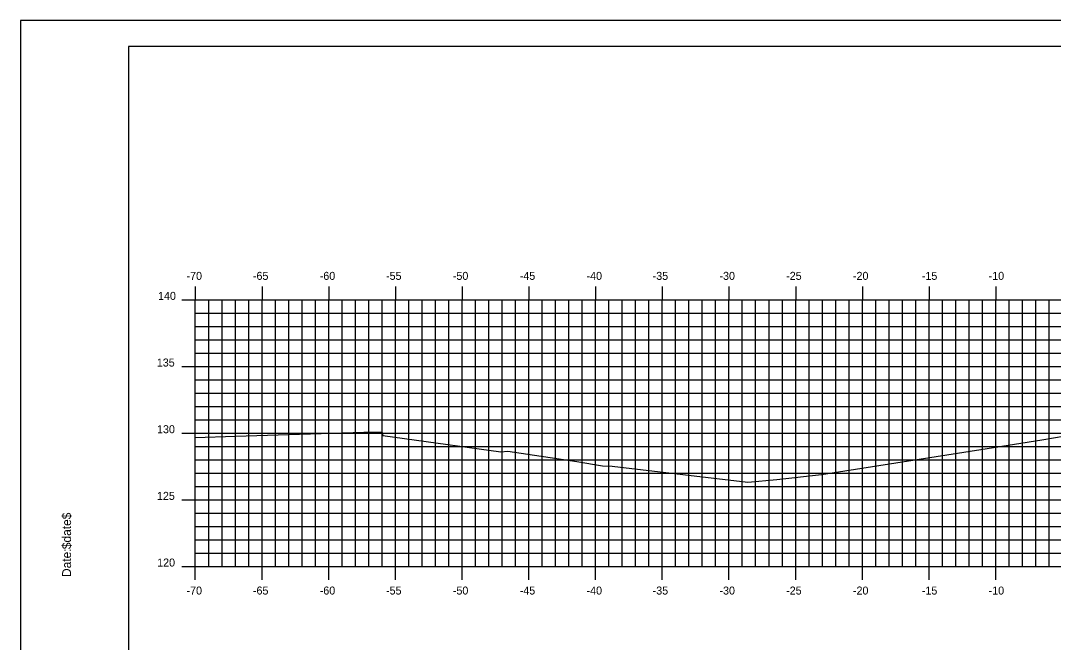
# Model space of a CAD drawing. Extents: x 850851 to 851023, y 365624 to 365734.
# Drawn here: x 850851.4 to 850928.8, y 365687.3 to 365734 of the extents above; entities that cross this region are included whole.
import ezdxf

# ---------------------------------------------------------------- set-up
doc = ezdxf.new("R2010")
doc.units = 0
for name, color, linetype in [('BORDER', 7, 'Continuous'), ('H_V ANNOTATION', 7, 'Continuous'), ('MAJOR', 7, 'Continuous'), ('MINOR', 7, 'Continuous'), ('PLOT BOUNDARY', 7, 'Continuous'), ('S_Roadway_Centerline', 7, 'Continuous')]:
    doc.layers.add(name, color=color, linetype=linetype)

msp = doc.modelspace()

# ---------------------------------------------------------------- linework, layer by layer
at = {"layer": 'BORDER'}
msp.add_lwpolyline([(850859.496, 365627.027), (851019.496, 365627.027), (851019.496, 365732.027), (850859.496, 365732.027)], close=True, dxfattribs=at)
at = {"layer": 'MAJOR'}
for p, q in [((850864.496, 365714.029), (850864.496, 365713.027)), ((850869.496, 365714.029), (850869.496, 365713.027)), ((850874.496, 365714.029), (850874.496, 365713.027)), ((850879.496, 365714.029), (850879.496, 365713.027)), ((850884.496, 365714.029), (850884.496, 365713.027)), ((850889.496, 365714.029), (850889.496, 365713.027)), ((850894.496, 365714.029), (850894.496, 365713.027)), ((850899.496, 365714.029), (850899.496, 365713.027)), ((850904.496, 365714.029), (850904.496, 365713.027)), ((850909.496, 365714.029), (850909.496, 365713.027)), ((850914.496, 365714.029), (850914.496, 365713.027)), ((850919.496, 365714.029), (850919.496, 365713.027)), ((850924.496, 365714.029), (850924.496, 365713.027)), ((850863.494, 365713.027), (850864.496, 365713.027)), ((850864.496, 365713.027), (851004.496, 365713.027)), ((850864.496, 365693.027), (850864.496, 365713.027)), ((850864.496, 365693.027), (850864.496, 365713.027)), ((850864.496, 365713.027), (851004.496, 365713.027)), ((850869.496, 365693.027), (850869.496, 365713.027)), ((850874.496, 365693.027), (850874.496, 365713.027)), ((850879.496, 365693.027), (850879.496, 365713.027)), ((850884.496, 365693.027), (850884.496, 365713.027)), ((850889.496, 365693.027), (850889.496, 365713.027)), ((850894.496, 365693.027), (850894.496, 365713.027)), ((850899.496, 365693.027), (850899.496, 365713.027)), ((850904.496, 365693.027), (850904.496, 365713.027)), ((850909.496, 365693.027), (850909.496, 365713.027)), ((850914.496, 365693.027), (850914.496, 365713.027)), ((850919.496, 365693.027), (850919.496, 365713.027)), ((850924.496, 365693.027), (850924.496, 365713.027)), ((850863.494, 365708.027), (850864.496, 365708.027)), ((850864.496, 365708.027), (851004.496, 365708.027)), ((850863.494, 365703.027), (850864.496, 365703.027)), ((850864.496, 365703.027), (851004.496, 365703.027)), ((850863.494, 365698.027), (850864.496, 365698.027)), ((850864.496, 365698.027), (851004.496, 365698.027)), ((850863.494, 365693.027), (850864.496, 365693.027)), ((850864.496, 365693.027), (851004.496, 365693.027)), ((850864.496, 365693.027), (851004.496, 365693.027)), ((850864.496, 365692.025), (850864.496, 365693.027)), ((850869.496, 365692.025), (850869.496, 365693.027)), ((850874.496, 365692.025), (850874.496, 365693.027)), ((850879.496, 365692.025), (850879.496, 365693.027)), ((850884.496, 365692.025), (850884.496, 365693.027)), ((850889.496, 365692.025), (850889.496, 365693.027)), ((850894.496, 365692.025), (850894.496, 365693.027)), ((850899.496, 365692.025), (850899.496, 365693.027)), ((850904.496, 365692.025), (850904.496, 365693.027)), ((850909.496, 365692.025), (850909.496, 365693.027)), ((850914.496, 365692.025), (850914.496, 365693.027)), ((850919.496, 365692.025), (850919.496, 365693.027)), ((850924.496, 365692.025), (850924.496, 365693.027))]:
    msp.add_line(p, q, dxfattribs=at)
at = {"layer": 'MINOR'}
for p, q in [((850865.496, 365693.027), (850865.496, 365713.027)), ((850866.496, 365693.027), (850866.496, 365713.027)), ((850867.496, 365693.027), (850867.496, 365713.027)), ((850868.496, 365693.027), (850868.496, 365713.027)), ((850870.496, 365693.027), (850870.496, 365713.027)), ((850871.496, 365693.027), (850871.496, 365713.027)), ((850872.496, 365693.027), (850872.496, 365713.027)), ((850873.496, 365693.027), (850873.496, 365713.027)), ((850875.496, 365693.027), (850875.496, 365713.027)), ((850876.496, 365693.027), (850876.496, 365713.027)), ((850877.496, 365693.027), (850877.496, 365713.027)), ((850878.496, 365693.027), (850878.496, 365713.027)), ((850880.496, 365693.027), (850880.496, 365713.027)), ((850881.496, 365693.027), (850881.496, 365713.027)), ((850882.496, 365693.027), (850882.496, 365713.027)), ((850883.496, 365693.027), (850883.496, 365713.027)), ((850885.496, 365693.027), (850885.496, 365713.027)), ((850886.496, 365693.027), (850886.496, 365713.027)), ((850887.496, 365693.027), (850887.496, 365713.027)), ((850888.496, 365693.027), (850888.496, 365713.027)), ((850890.496, 365693.027), (850890.496, 365713.027)), ((850891.496, 365693.027), (850891.496, 365713.027)), ((850892.496, 365693.027), (850892.496, 365713.027)), ((850893.496, 365693.027), (850893.496, 365713.027)), ((850895.496, 365693.027), (850895.496, 365713.027)), ((850896.496, 365693.027), (850896.496, 365713.027)), ((850897.496, 365693.027), (850897.496, 365713.027)), ((850898.496, 365693.027), (850898.496, 365713.027)), ((850900.496, 365693.027), (850900.496, 365713.027)), ((850901.496, 365693.027), (850901.496, 365713.027)), ((850902.496, 365693.027), (850902.496, 365713.027)), ((850903.496, 365693.027), (850903.496, 365713.027)), ((850905.496, 365693.027), (850905.496, 365713.027)), ((850906.496, 365693.027), (850906.496, 365713.027)), ((850907.496, 365693.027), (850907.496, 365713.027)), ((850908.496, 365693.027), (850908.496, 365713.027)), ((850910.496, 365693.027), (850910.496, 365713.027)), ((850911.496, 365693.027), (850911.496, 365713.027)), ((850912.496, 365693.027), (850912.496, 365713.027)), ((850913.496, 365693.027), (850913.496, 365713.027)), ((850915.496, 365693.027), (850915.496, 365713.027)), ((850916.496, 365693.027), (850916.496, 365713.027)), ((850917.496, 365693.027), (850917.496, 365713.027)), ((850918.496, 365693.027), (850918.496, 365713.027)), ((850920.496, 365693.027), (850920.496, 365713.027)), ((850921.496, 365693.027), (850921.496, 365713.027)), ((850922.496, 365693.027), (850922.496, 365713.027)), ((850923.496, 365693.027), (850923.496, 365713.027)), ((850925.496, 365693.027), (850925.496, 365713.027)), ((850926.496, 365693.027), (850926.496, 365713.027)), ((850927.496, 365693.027), (850927.496, 365713.027)), ((850928.496, 365693.027), (850928.496, 365713.027)), ((850864.496, 365712.027), (851004.496, 365712.027)), ((850864.496, 365712.027), (850865.498, 365712.027)), ((850864.496, 365711.027), (851004.496, 365711.027)), ((850864.496, 365711.027), (850865.498, 365711.027)), ((850864.496, 365710.027), (851004.496, 365710.027)), ((850864.496, 365710.027), (850865.498, 365710.027)), ((850864.496, 365709.027), (851004.496, 365709.027)), ((850864.496, 365709.027), (850865.498, 365709.027)), ((850864.496, 365707.027), (851004.496, 365707.027)), ((850864.496, 365707.027), (850865.498, 365707.027)), ((850864.496, 365706.027), (851004.496, 365706.027)), ((850864.496, 365706.027), (850865.498, 365706.027)), ((850864.496, 365705.027), (851004.496, 365705.027)), ((850864.496, 365705.027), (850865.498, 365705.027)), ((850864.496, 365704.027), (851004.496, 365704.027)), ((850864.496, 365704.027), (850865.498, 365704.027)), ((850864.496, 365702.027), (851004.496, 365702.027)), ((850864.496, 365702.027), (850865.498, 365702.027)), ((850864.496, 365701.027), (851004.496, 365701.027)), ((850864.496, 365701.027), (850865.498, 365701.027)), ((850864.496, 365700.027), (851004.496, 365700.027)), ((850864.496, 365700.027), (850865.498, 365700.027)), ((850864.496, 365699.027), (851004.496, 365699.027)), ((850864.496, 365699.027), (850865.498, 365699.027)), ((850864.496, 365697.027), (851004.496, 365697.027)), ((850864.496, 365697.027), (850865.498, 365697.027)), ((850864.496, 365696.027), (851004.496, 365696.027)), ((850864.496, 365696.027), (850865.498, 365696.027)), ((850864.496, 365695.027), (851004.496, 365695.027)), ((850864.496, 365695.027), (850865.498, 365695.027)), ((850864.496, 365694.027), (851004.496, 365694.027)), ((850864.496, 365694.027), (850865.498, 365694.027))]:
    msp.add_line(p, q, dxfattribs=at)
at = {"layer": 'PLOT BOUNDARY'}
msp.add_lwpolyline([(850851.403, 365623.968), (851021.403, 365623.968), (851021.403, 365733.968), (850851.403, 365733.968)], close=True, dxfattribs=at)
at = {"layer": 'S_Roadway_Centerline'}
msp.add_lwpolyline([(850864.496, 365702.701), (850867.506, 365702.808), (850877.134, 365703.096), (850878.483, 365703.128), (850878.558, 365702.846), (850880.182, 365702.631), (850887.406, 365701.637), (850887.932, 365701.686), (850893.096, 365700.893), (850895.02, 365700.589), (850895.731, 365700.548), (850905.905, 365699.354), (850908.071, 365699.548), (850911.42, 365699.923), (850923.839, 365701.868), (850927.954, 365702.525), (850929.707, 365702.822)], dxfattribs=at)

# ---------------------------------------------------------------- texts
at = {"layer": 'BORDER'}
for s, p in [('$date$', (850855.181, 365694.332)), ('Date:', (850855.181, 365692.244))]:
    msp.add_text(s, height=0.6696, rotation=90, dxfattribs=at).set_placement(p)
at = {"layer": 'H_V ANNOTATION'}
for s, p in [('-70', (850863.838, 365714.527)), ('-65', (850868.814, 365714.527)), ('-60', (850873.822, 365714.527)), ('-55', (850878.792, 365714.527)), ('-50', (850883.8, 365714.527)), ('-45', (850888.814, 365714.527)), ('-40', (850893.822, 365714.527)), ('-35', (850898.776, 365714.527)), ('-30', (850903.784, 365714.527)), ('-25', (850908.782, 365714.527)), ('-20', (850913.79, 365714.527)), ('-15', (850918.953, 365714.527)), ('-10', (850923.961, 365714.527)), ('140', (850861.701, 365713.027)), ('135', (850861.61, 365708.027)), ('130', (850861.626, 365703.027)), ('125', (850861.621, 365698.027)), ('120', (850861.637, 365693.027)), ('-70', (850863.838, 365690.927)), ('-65', (850868.814, 365690.927)), ('-60', (850873.822, 365690.927)), ('-55', (850878.792, 365690.927)), ('-50', (850883.8, 365690.927)), ('-45', (850888.814, 365690.927)), ('-40', (850893.822, 365690.927)), ('-35', (850898.776, 365690.927)), ('-30', (850903.784, 365690.927)), ('-25', (850908.782, 365690.927)), ('-20', (850913.79, 365690.927)), ('-15', (850918.953, 365690.927)), ('-10', (850923.961, 365690.927))]:
    msp.add_text(s, height=0.6, dxfattribs=at).set_placement(p)
at = {"layer": 'MAJOR'}
msp.add_text('-', height=0.006, dxfattribs=at).set_placement((850864.492, 365693.027))

doc.saveas('drawing.dxf')
